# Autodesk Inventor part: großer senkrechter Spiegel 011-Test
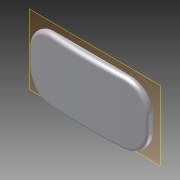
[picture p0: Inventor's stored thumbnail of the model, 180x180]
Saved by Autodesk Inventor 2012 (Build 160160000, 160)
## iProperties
Created: 2012-09
Part Number: großer senkrechter Spiegel 011-Test
Material: Default
Document SubType Name: Modeling
Designer: Hans-Jürgen
Density: 1 g/cm^3
Author: Hans-Jürgen
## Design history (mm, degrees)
sketch "Skizze1"
  geometry: L1 (0, 1.003)-(0.497, 0.948); L2 (-0.497, 0.054)-(-0.497, 1.061); L3 (17.203, -0.055)-(17.203, 0.951); A1 r 79.072 centre (8.838, 78.573) between (-0.497, 0.054) and (17.203, -0.055); A2 r 78.072 centre (8.838, 78.573) between (-0.497, 1.061) and (17.203, 0.951); 1 further point
  constraints: 6 end point, 6 point on circle, 2 centre point, 1 parallel, 1 vertical
  dimensions: "d3" = 0.5 distance of point (0, 0) L2.start; "d5" = 1 radial gap between concentric circles of A2 A1; "d25" = 17.7 horizontal distance of L3.start L2.start
extrude "Extrusion1" new body sketch "Skizze1" stored distance "d6" = 9.3; taper "d7" = 0 deg
fillet "Rundung4" dims "d26" = 3.5
feature "Wandstärke3" dims "d27" = 0.5
fillet "Rundung7" dims "d30" = 0.5
fillet "Rundung8" dims "d31" = 0.4
fillet "Rundung10" dims "d33" = 0.8
workplane "Arbeitsebene3"
sketch "Skizze4"
  geometry: L1 (1.15, 16.757)-(-1.15, 16.757) reference; L2 (4.15, 3.055)-(4.15, 13.755) reference; L3 (-1.15, 0.056)-(1.15, 0.056) reference; L4 (-4.15, 13.755)-(-4.15, 3.055) reference; 1 further point
  constraints: 4 other
extrude "Extrusion4" join sketch "Skizze4" distance "d34" = 0.5; taper "d35" = 0 deg
node "Volumenkörper1"
node "Projizierte Kontur3"
